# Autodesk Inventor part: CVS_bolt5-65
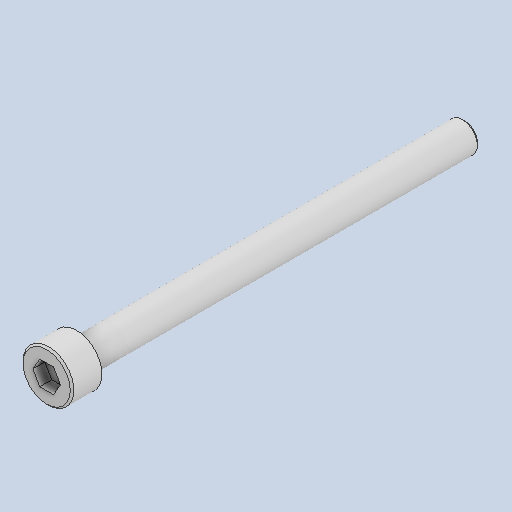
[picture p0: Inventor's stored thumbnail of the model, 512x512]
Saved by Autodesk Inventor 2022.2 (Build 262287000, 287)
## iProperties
Created: 2024-10
Part Number: CVS_bolt5-65
Material: Generico
Document SubType Name: Modeling
Designer: 18907419
Density: 1 g/cm^3
Appearance: Default
Author: 18907419
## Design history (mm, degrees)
feature "Solido1"
node "Solido2"
